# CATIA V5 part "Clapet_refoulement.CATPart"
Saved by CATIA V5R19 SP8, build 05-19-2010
Part number: Clapet_refoulement
Revision: ANY
Definition: UNKNOWN
Nomenclature: 14
Source: Unknown
Bounding box of the stored display mesh (mm): x 7 to 10, y -3.5 to 3.5, z -3.5 to 3.5
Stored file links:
  D:\Documents\1_Travail\2- 2I2D\1 - Cours et TD\2- TD\3-TD Assemblage\Pompe AirMan\Clapet_refoulement.CATPart
  D:\Documents\1_Travail\2- 2I2D\1 - Cours et TD\2- TD\3-TD Assemblage\Pompe AirMan\0-PompeAirman.CATProduct
  D:\Documents\1_Travail\2- 2I2D\1 - Cours et TD\2- TD\3-TD Assemblage\Pompe AirMan\Embout_corps_cylindre.CATPart
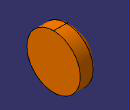
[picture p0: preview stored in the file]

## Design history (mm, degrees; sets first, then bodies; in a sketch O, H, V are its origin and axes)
Set1
  DatumCurve1: linked copy from another document
Set2
  Sketch1 on xy-plane, origin (0, 0, 0), H (1, 0, 0), V (0, 1, 0)
    line L1 (0, 0) -> (1, 2)
    point P1 (1, 2)
    line L2 (1, 2) -> (7.4, 2)
    point P2 (7.4, 2)
    line L3 (7.4, 2) -> (8.4, 0)
    point P3 (8.4, 0)
    reference projected line E1 through (0, 0) direction (-1, 0) from edge of DatumCurve1
    line L4 (8.4, 0) -> (16.8, 0)
    point P5 (17.8, 2)
    point P6 (16.8, 0)
    line L5 (16.8, 0) -> (17.8, 2)
    point P7 (24.2, 2)
    line L6 (17.8, 2) -> (24.2, 2)
    point P8 (25.2, 0)
    line L7 (24.2, 2) -> (25.2, 0)
    line L8 (25.2, 0) -> (33.6, 0)
    point P10 (34.6, 2)
    point P11 (33.6, 0)
    line L9 (33.6, 0) -> (34.6, 2)
    point P12 (41, 2)
    line L10 (34.6, 2) -> (41, 2)
    point P13 (42, 0)
    line L11 (41, 2) -> (42, 0)
    line L12 (42, 0) -> (50.4, 0)
    point P15 (51.4, 2)
    point P16 (50.4, 0)
    line L13 (50.4, 0) -> (51.4, 2)
    point P17 (57.8, 2)
    line L14 (51.4, 2) -> (57.8, 2)
    point P18 (58.8, 0)
    line L15 (57.8, 2) -> (58.8, 0)
    line L16 (58.8, 0) -> (67.2, 0)
    point P20 (67.2, 0)
    distance L2 E1 = 2
    distance P1 V = 1
    distance P3 P2 H = 1
    distance P3 O = 8.4
    length L4 H = 8.4
    distance P8 P7 H = 1
    length L8 H = 8.4
    distance P8 P6 = 8.4
    distance L6 E1 = 2 (reference)
    distance P5 V = 17.8 (reference)
    length L12 H = 8.4
    distance P13 P12 H = 1
    distance P13 P11 = 8.4
    distance L10 E1 = 2 (reference)
    distance P10 V = 34.6 (reference)
    length L16 H = 8.4
    distance P18 P17 H = 1
    distance P18 P16 = 8.4
    distance L14 E1 = 2 (reference)
    distance P15 V = 51.4 (reference)
    horizontal: L2 H, L4 H, L6 H, L8 H, L12 H, L10 H, L16 H, L14 H
    coincidence: P3 H
  Sketch2 on xy-plane, origin (0, 0, 0), H (1, 0, 0), V (0, 1, 0)
    line L1 (0, 0) -> (1, 2)
    point P1 (1, 2)
    line L2 (1, 2) -> (7.4, 2)
    point P2 (7.4, 2)
    line L3 (7.4, 2) -> (8.4, 0)
    point P3 (8.4, 0)
    line L4 (8.4, 0) -> (16.8, 0)
    point P4 (16.8, 0)
    line L5 (16.8, 0) -> (17.8, 2)
    point P5 (17.8, 2)
    line L6 (17.8, 2) -> (24.2, 2)
    line L7 (24.2, 2) -> (25.2, 0)
    point P7 (25.2, 0)
    line L8 (25.2, 0) -> (33.6, 0)
    point P8 (33.6, 0)
    line L9 (33.6, 0) -> (34.6, 2)
    point P9 (34.6, 2)
    line L10 (34.6, 2) -> (41, 2)
    line L11 (41, 2) -> (42, 0)
    point P11 (42, 0)
    line L12 (42, 0) -> (50.4, 0)
    point P12 (50.4, 0)
    line L13 (50.4, 0) -> (51.4, 2)
    point P13 (51.4, 2)
    line L14 (51.4, 2) -> (57.8, 2)
    line L15 (57.8, 2) -> (58.8, 0)
    point P15 (58.8, 0)
    line L16 (58.8, 0) -> (67.2, 0)
    distance L2 H = 2
    distance P1 V = 1
    distance P2 P3 H = 1
    distance O P3 = 8.4
    distance P3 P4 = 8.4
    distance P4 P7 = 8.4
    length L8 = 8.4
    distance P8 P11 = 8.4
    length L12 = 8.4
    distance P12 P15 = 8.4
    length L16 = 8.4
    horizontal: L2 H, L4 H, L6 H, L8 H, L10 H, L12 H, L14 H, L16 H
    coincidence: P3 H, P5 L2, P7 H, P9 L6, P11 H, P13 L10, P15 L12
    parallelism: L5 L1, L7 L3, L9 L5, L11 L7, L13 L9, L15 L11
  Sketch3 on xy-plane, origin (0, 0, 0), H (1, 0, 0), V (0, 1, 0)
    spline S1 through (0, 0) (0.9133, 1.9402) (7.3291, 1.9402) (8.2914, 0) (16.7237, 0) (17.6402, 1.9402) (24.2852, 1.9402) (25.0642, 0) (33.7255, 0) (34.5504, 1.9402) (41.1954, 1.9402) (41.9286, 0) (50.4066, 0) (51.4607, 1.9402) (57.7809, 1.9922) (58.7952, 0) (66.9537, 0)
    point P1 (0, 0)
    point P2 (8.2914, 0)
    point P3 (16.7237, 0)
    point P4 (25.0642, 0)
    point P5 (33.7255, 0)
    point P6 (41.9286, 0)
    point P7 (50.4066, 0)
    point P8 (58.7952, 0)
    point P9 (66.9537, 0)
    coincidence: P1 O, P2 H, P3 H, P4 H, P5 H, P6 H, P7 H, P8 H, P9 H
Body1 "Congé1" (main body)
  Solid1: solid without history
